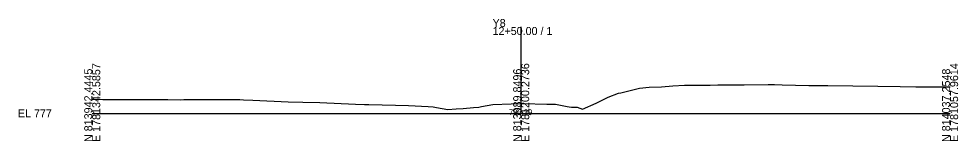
# Model space of a CAD drawing. Extents: x -26 to 303, y -10 to 5036.
# Drawn here: x -25.7 to 302.8, y 4490.3 to 4533 of the extents above; entities that cross this region are included whole.
import ezdxf

# ---------------------------------------------------------------- set-up
doc = ezdxf.new("R2010")
doc.units = 0
for name, color, linetype in [('Exist Cross Section Cell', 7, 'Continuous'), ('Exist XS Center Line Elevation Label', 7, 'Continuous'), ('Exist XS Ground Line', 7, 'Continuous')]:
    doc.layers.add(name, color=color, linetype=linetype)

msp = doc.modelspace()

# ---------------------------------------------------------------- linework, layer by layer
at = {"layer": 'Exist Cross Section Cell'}
for p, q in [((150, 4500), (150, 4530.12)), ((0, 4500), (150, 4500)), ((150, 4500), (300, 4500))]:
    msp.add_line(p, q, dxfattribs=at)
at = {"layer": 'Exist XS Ground Line'}
for p, q in [((184.87, 4507.19), (191.38, 4508.83)), ((191.38, 4508.83), (194.73, 4509.12)), ((194.73, 4509.12), (199.03, 4509.31)), ((199.03, 4509.31), (203.08, 4509.55)), ((203.08, 4509.55), (207.17, 4509.85)), ((207.17, 4509.85), (216.05, 4509.86)), ((216.05, 4509.86), (218.82, 4509.9)), ((218.82, 4509.9), (220.26, 4509.93)), ((220.26, 4509.93), (228.02, 4509.97)), ((228.02, 4509.97), (236.4, 4510.04)), ((236.4, 4510.04), (238.64, 4510.02)), ((238.64, 4510.02), (241.22, 4509.99)), ((241.22, 4509.99), (250.61, 4509.74)), ((250.61, 4509.74), (257.22, 4509.76)), ((257.22, 4509.76), (265.93, 4509.62)), ((265.93, 4509.62), (274.75, 4509.46)), ((274.75, 4509.46), (282.52, 4509.35)), ((282.52, 4509.35), (288.01, 4509.27)), ((288.01, 4509.27), (296.6, 4509.24)), ((296.6, 4509.24), (300, 4509.21)), ((0, 4504.87), (2.46, 4504.9)), ((2.46, 4504.9), (3.74, 4504.89)), ((3.74, 4504.89), (14.69, 4504.88)), ((14.69, 4504.88), (26.38, 4504.84)), ((26.38, 4504.84), (30.76, 4504.72)), ((30.76, 4504.72), (31.98, 4504.88)), ((31.98, 4504.88), (51.58, 4504.78)), ((51.58, 4504.78), (52.93, 4504.7)), ((52.93, 4504.7), (56.17, 4504.62)), ((56.17, 4504.62), (68.47, 4504.07)), ((176.22, 4503.57), (180.45, 4505.66)), ((180.45, 4505.66), (184.08, 4507.01)), ((184.08, 4507.01), (184.87, 4507.19)), ((68.47, 4504.07), (73.65, 4503.89)), ((73.65, 4503.89), (79.62, 4503.76)), ((79.62, 4503.76), (92.01, 4503.22)), ((92.01, 4503.22), (95.22, 4503.1)), ((95.22, 4503.1), (96.76, 4503.07)), ((96.76, 4503.07), (106.01, 4502.88)), ((106.01, 4502.88), (110.58, 4502.69)), ((110.58, 4502.69), (117.53, 4502.4)), ((117.53, 4502.4), (119.24, 4502.29)), ((119.24, 4502.29), (120.43, 4502.08)), ((120.43, 4502.08), (124.4, 4501.32)), ((124.4, 4501.32), (127.24, 4501.56)), ((127.24, 4501.56), (129.72, 4501.66)), ((129.72, 4501.66), (133.38, 4502.08)), ((133.38, 4502.08), (135.15, 4502.2)), ((135.15, 4502.2), (136.1, 4502.43)), ((136.1, 4502.43), (140.11, 4503.14)), ((140.11, 4503.14), (146.55, 4503.31)), ((146.55, 4503.31), (150, 4503.39)), ((150, 4503.39), (150.64, 4503.41)), ((150.64, 4503.41), (159, 4503.22)), ((159, 4503.22), (162, 4503.15)), ((162, 4503.15), (166.04, 4502.4)), ((166.04, 4502.4), (166.78, 4502.24)), ((166.78, 4502.24), (167.61, 4502.15)), ((167.61, 4502.15), (169.62, 4502.14)), ((169.62, 4502.14), (171.48, 4501.45)), ((171.48, 4501.45), (176.22, 4503.57))]:
    msp.add_line(p, q, dxfattribs=at)

# ---------------------------------------------------------------- texts
at = {"layer": 'Exist Cross Section Cell'}
for s, p in [('Y8', (140, 4530.12)), ('12+50.00 / 1', (140, 4527.32)), ('EL 777', (-26, 4498.6))]:
    msp.add_text(s, height=2.8, dxfattribs=at).set_placement(p)
for s, p in [('E 1781057.9614', (302.8, 4490)), ('N 813942.4445', (0, 4490)), ('E 1781342.5857', (2.8, 4490)), ('N 813989.8496', (150, 4490)), ('E 1781200.2736', (152.8, 4490)), ('N 814037.2548', (300, 4490))]:
    msp.add_text(s, height=2.8, rotation=90, dxfattribs=at).set_placement(p)
at = {"layer": 'Exist XS Center Line Elevation Label'}
msp.add_text('780.39', height=2, dxfattribs=at).set_placement((145.73, 4499.39))

doc.saveas('drawing.dxf')
